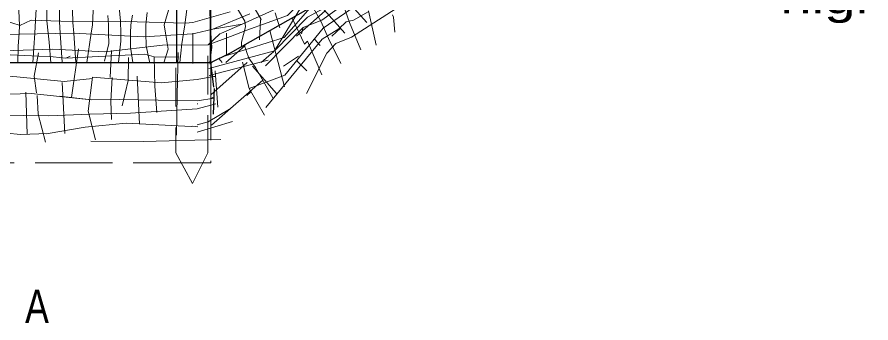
# Model space of a CAD drawing. Extents: x 1083.1 to 1117.1, y 672.5 to 716.5.
# Drawn here: x 1093.956 to 1098.058, y 709.948 to 711.418 of the extents above; entities that cross this region are included whole.
import ezdxf
from ezdxf.enums import TextEntityAlignment as Align

# ---------------------------------------------------------------- set-up
doc = ezdxf.new("R2010")
doc.units = 0
doc.header["$LTSCALE"] = 0.062
doc.linetypes.add('LONG_DASHED', pattern=[7.5, 6, -1.5])
doc.linetypes.add('MEDIUM_DASHED', pattern=[4.5, 3, -1.5])
doc.layers.add('1', color=7, linetype='Continuous', lineweight=13)

msp = doc.modelspace()

# ---------------------------------------------------------------- linework, layer by layer
at = {"layer": '1', "lineweight": 25}
for p, q in [((1094.98183, 711.247), (1098.69967, 713.3535)), ((1094.72208, 712.82583), (1094.72208, 711.20083)), ((1094.88383, 712.82583), (1094.88383, 711.19133)), ((1094.88667, 711.19942), (1094.98183, 711.247)), ((1091.47983, 711.19942), (1094.88667, 711.19942)), ((1094.90133, 711.08083), (1094.88667, 711.19942)), ((1094.89983, 710.95233), (1094.90467, 711.07442))]:
    msp.add_line(p, q, dxfattribs=at)
at = {"layer": '1'}
for p, q in [((1094.04458, 711.40167), (1094.0705, 711.79283)), ((1094.22492, 711.39167), (1094.21133, 711.768)), ((1095.44575, 711.60675), (1095.63625, 711.39142)), ((1094.95658, 711.556), (1095.05117, 711.39783)), ((1095.19258, 711.25575), (1095.36125, 711.53283)), ((1095.34167, 711.55475), (1095.5315, 711.34017)), ((1095.56717, 711.53617), (1095.35125, 711.41742)), ((1095.07175, 711.50775), (1095.12933, 711.4065)), ((1095.55317, 711.3915), (1095.51583, 711.49642)), ((1095.84, 711.50142), (1095.56283, 711.32108)), ((1094.32325, 711.48133), (1094.31858, 711.38033)), ((1094.69125, 711.47833), (1094.66233, 711.38033)), ((1094.77175, 711.45508), (1094.76283, 711.38033)), ((1095.36492, 711.46267), (1095.2395, 711.31933)), ((1095.29858, 711.32725), (1095.43575, 711.44858)), ((1095.41625, 711.398), (1095.37575, 711.46875)), ((1095.682, 711.28283), (1095.64483, 711.44775)), ((1094.39175, 711.42658), (1094.395, 711.38033)), ((1094.51142, 711.42683), (1094.50258, 711.38033)), ((1094.58058, 711.44), (1094.57542, 711.38033)), ((1094.80108, 711.3925), (1094.9805, 711.44392)), ((1095.07425, 711.4335), (1094.89725, 711.3595)), ((1095.35125, 711.41742), (1095.19275, 711.25608)), ((1095.19667, 711.43817), (1095.21867, 711.366)), ((1095.33717, 711.28725), (1095.27733, 711.41375)), ((1094.02492, 711.40308), (1093.96908, 711.378)), ((1094.02492, 711.40308), (1094.16708, 711.39875)), ((1094.76575, 711.38842), (1094.80108, 711.3925)), ((1095.03708, 711.38467), (1094.89725, 711.3595)), ((1094.93775, 711.34133), (1095.03708, 711.38467)), ((1095.05117, 711.39783), (1095.05308, 711.37083)), ((1095.3305, 711.36825), (1095.14967, 711.18367)), ((1095.42708, 711.36533), (1095.24258, 711.13975)), ((1095.3305, 711.36825), (1095.32258, 711.33817)), ((1095.4685, 711.32725), (1095.51025, 711.36442)), ((1095.53733, 711.39517), (1095.50283, 711.36133)), ((1095.60717, 711.26058), (1095.55317, 711.3915)), ((1094.80058, 711.34133), (1094.80058, 711.19592)), ((1094.87408, 711.28517), (1094.98183, 711.32558)), ((1094.93058, 711.33825), (1094.93775, 711.34133)), ((1094.96233, 711.34133), (1094.96233, 711.23933)), ((1094.98183, 711.32558), (1095.05958, 711.35475)), ((1095.171, 711.35417), (1095.24125, 711.08325)), ((1095.50283, 711.36133), (1095.422, 711.31258)), ((1094.11008, 711.29833), (1094.11825, 711.199)), ((1094.39767, 711.29067), (1094.37675, 711.20667)), ((1094.45475, 711.30275), (1094.44308, 711.20117)), ((1094.74808, 711.28958), (1094.73767, 711.20008)), ((1094.95875, 711.19942), (1095.05242, 711.28225)), ((1095.2395, 711.31933), (1094.99367, 711.24308)), ((1095.06933, 711.22117), (1095.04675, 711.28467)), ((1095.422, 711.31258), (1095.15117, 710.98317)), ((1095.41967, 711.141), (1095.352, 711.30317)), ((1095.38675, 711.31083), (1095.41242, 711.28183)), ((1095.48792, 711.29083), (1095.4445, 711.24508)), ((1095.56283, 711.32108), (1095.48792, 711.29083)), ((1093.96183, 711.27875), (1093.9595, 711.19692)), ((1094.0375, 711.27117), (1094.03283, 711.19908)), ((1094.03808, 711.13417), (1094.05992, 711.247)), ((1094.21767, 711.03108), (1094.25175, 711.2655)), ((1094.4035, 711.1285), (1094.40983, 711.25708)), ((1094.50125, 711.27325), (1094.51292, 711.20008)), ((1094.57583, 711.27975), (1094.59442, 711.19683)), ((1094.68292, 711.26342), (1094.66083, 711.19792)), ((1095.19275, 711.25608), (1094.87767, 711.17125)), ((1094.89158, 711.27267), (1094.88158, 711.20117)), ((1094.94567, 711.22808), (1094.99367, 711.24308)), ((1095.12892, 711.19942), (1095.18917, 711.25267)), ((1095.34733, 711.05025), (1095.4445, 711.24508)), ((1093.9235, 711.23625), (1094.13008, 711.22725)), ((1094.13008, 711.22725), (1094.19125, 711.22)), ((1094.49008, 711.1135), (1094.49242, 711.22475)), ((1094.6155, 711.22767), (1094.73508, 711.22492)), ((1094.87925, 711.13775), (1095.16317, 711.21175)), ((1094.92517, 711.21867), (1094.94217, 711.19942)), ((1095.07158, 711.07575), (1095.03967, 711.20108)), ((1095.23675, 711.18292), (1095.30767, 711.2305)), ((1095.34783, 711.16), (1095.29842, 711.20992)), ((1094.88667, 711.195), (1094.89167, 711.19942)), ((1094.88667, 711.04467), (1095.06183, 711.19942)), ((1094.90842, 711.16008), (1094.92125, 710.98492)), ((1095.08667, 711.18275), (1095.20292, 711.05133)), ((1095.10192, 711.17525), (1095.18483, 711.03025)), ((1094.05033, 711.05408), (1094.03808, 711.13417)), ((1094.1825, 711.10917), (1094.31908, 711.12283)), ((1094.40742, 711.01383), (1094.41317, 711.12775)), ((1094.54433, 710.90425), (1094.53317, 711.13383)), ((1094.64808, 711.10217), (1094.82192, 711.11892)), ((1094.82192, 711.11892), (1094.90033, 711.133)), ((1094.90033, 711.133), (1094.90983, 711.13242)), ((1095.24258, 711.13975), (1095.07158, 711.07575)), ((1094.1725, 711.104), (1094.18592, 710.85825)), ((1094.46142, 710.99233), (1094.49008, 711.1135)), ((1094.89108, 710.89858), (1095.13642, 711.11542)), ((1094.00475, 710.855), (1093.99875, 711.05783)), ((1094.05292, 711.04217), (1094.05808, 710.95092)), ((1094.31392, 711.0205), (1094.1595, 711.0375)), ((1095.05983, 711.04158), (1095.0795, 711.05908)), ((1095.07158, 711.07575), (1095.14517, 710.94675)), ((1094.4095, 710.92567), (1094.40742, 711.01383)), ((1094.821, 711.00175), (1094.82433, 711.00175)), ((1094.90258, 711.02933), (1094.82192, 711.01642)), ((1094.82192, 710.97675), (1094.91058, 711.00192)), ((1094.88492, 711.02633), (1094.90042, 711.03267)), ((1094.82192, 710.97675), (1094.50158, 710.95608)), ((1094.97617, 710.97575), (1094.87508, 710.915)), ((1093.75225, 710.94892), (1094.10958, 710.94425)), ((1094.05808, 710.95092), (1094.09375, 710.81642)), ((1094.82192, 710.86558), (1094.99183, 710.9165)), ((1094.82192, 710.9005), (1094.87508, 710.915)), ((1094.47992, 710.90892), (1094.51217, 710.90658)), ((1094.79292, 710.89233), (1094.51217, 710.90658)), ((1094.79292, 710.89233), (1094.79975, 710.89325)), ((1094.79975, 710.89325), (1094.82433, 710.89108)), ((1093.97242, 710.85442), (1093.90783, 710.86117)), ((1094.10533, 710.8595), (1093.97242, 710.85442)), ((1094.56283, 710.82083), (1094.3105, 710.82133)), ((1094.93533, 710.8295), (1094.56283, 710.82083))]:
    msp.add_line(p, q, dxfattribs=at)
at = {"layer": '1', "linetype": 'MEDIUM_DASHED'}
for p, q in [((1094.873, 711.23267), (1094.873, 710.76583)), ((1094.719, 711.17425), (1094.719, 710.76583)), ((1094.719, 710.76583), (1094.79917, 710.61883)), ((1094.79917, 710.61883), (1094.873, 710.76583))]:
    msp.add_line(p, q, dxfattribs=at)
at = {"layer": '1'}
for points in [[(1094.43817, 711.96875), (1094.44375, 711.73108), (1094.43633, 711.58558), (1094.45367, 711.398)], [(1094.16267, 711.83467), (1094.16017, 711.59392), (1094.16017, 711.39525)], [(1095.05958, 711.35475), (1095.25608, 711.42583), (1095.49575, 711.67175), (1095.78192, 711.81883)], [(1094.09925, 711.40067), (1094.09975, 711.67042), (1094.11067, 711.76058)], [(1093.96358, 711.6655), (1093.96125, 711.524), (1093.96867, 711.37775)], [(1095.42117, 711.40275), (1095.64808, 711.569), (1095.79392, 711.66242)], [(1095.42708, 711.36533), (1095.6785, 711.53975), (1095.8755, 711.65675)], [(1094.88083, 711.47408), (1094.88792, 711.34133), (1094.89158, 711.27267)], [(1095.03708, 711.38467), (1095.20125, 711.45767), (1095.22025, 711.46975)], [(1093.69192, 711.40308), (1093.77825, 711.41267), (1093.89117, 711.40342), (1093.97117, 711.378)], [(1095.12933, 711.4065), (1095.12608, 711.40317), (1095.12142, 711.30925)], [(1095.64283, 711.44417), (1095.57292, 711.40267), (1095.53733, 711.39517)], [(1095.77075, 711.34575), (1095.764, 711.4175), (1095.75908, 711.4285)], [(1093.96867, 711.37775), (1093.96608, 711.34133), (1093.96183, 711.27875)], [(1094.04458, 711.40167), (1094.04125, 711.34133), (1094.0375, 711.27117)], [(1094.09925, 711.40067), (1094.1055, 711.34133), (1094.11008, 711.29833)], [(1094.16017, 711.39525), (1094.16375, 711.34133), (1094.173, 711.20117)], [(1094.16708, 711.39875), (1094.475, 711.39617), (1094.76575, 711.38842)], [(1094.22492, 711.39167), (1094.22875, 711.34133), (1094.23933, 711.199)], [(1094.31858, 711.38033), (1094.31275, 711.34133), (1094.29175, 711.20008)], [(1094.395, 711.38033), (1094.39617, 711.34133), (1094.39767, 711.29067)], [(1094.45367, 711.398), (1094.45433, 711.34133), (1094.45475, 711.30275)], [(1094.50258, 711.38033), (1094.50208, 711.34133), (1094.50125, 711.27325)], [(1094.57542, 711.38033), (1094.57558, 711.34133), (1094.57583, 711.27975)], [(1094.66233, 711.38033), (1094.66917, 711.34133), (1094.68292, 711.26342)], [(1094.76283, 711.38033), (1094.7565, 711.34133), (1094.74808, 711.28958)], [(1095.05308, 711.37083), (1095.03417, 711.29725), (1095.03417, 711.27433)], [(1095.42117, 711.40275), (1095.3305, 711.36825), (1095.32858, 711.36983)], [(1095.51233, 711.195), (1095.4525, 711.31533), (1095.41625, 711.398)], [(1093.88058, 711.33525), (1094.22583, 711.34017), (1094.5655, 711.324), (1094.79867, 711.33775)], [(1093.89092, 711.25608), (1094.12583, 711.26417), (1094.37758, 711.25125), (1094.65517, 711.28358), (1094.87408, 711.28517), (1094.93058, 711.33825)], [(1094.89725, 711.3595), (1094.81492, 711.34133), (1094.79867, 711.33775)], [(1095.352, 711.30317), (1095.33717, 711.28725), (1095.33517, 711.29342)], [(1094.72283, 710.85042), (1094.726, 711.04375), (1094.72975, 711.24875)], [(1094.57075, 711.23967), (1094.19125, 711.22), (1094.21117, 711.23025)], [(1094.628, 710.95983), (1094.61817, 711.08667), (1094.6155, 711.22767), (1094.57075, 711.23967)], [(1095.10192, 711.17525), (1095.06933, 711.22117), (1095.06725, 711.22525)], [(1093.783, 711.14417), (1093.95533, 711.13108), (1094.1825, 711.10917)], [(1094.3335, 710.8285), (1094.29833, 710.96592), (1094.31933, 711.12867), (1094.64808, 711.10217)], [(1093.60383, 711.0375), (1094.02492, 711.05158), (1094.31392, 711.0205)], [(1094.31392, 711.0205), (1094.44675, 711.02275), (1094.82192, 711.01642)], [(1094.50158, 710.95608), (1094.30567, 710.95183), (1094.10958, 710.94425)], [(1094.47992, 710.90892), (1094.28367, 710.88892), (1094.10533, 710.8595), (1094.09883, 710.85708)]]:
    msp.add_lwpolyline(points, dxfattribs=at)
msp.add_lwpolyline([(1091.47983, 711.19942), (1091.47983, 711.69942), (1094.88667, 711.69942), (1094.88667, 711.19942)], close=True, dxfattribs=at)
at = {"layer": '1', "linetype": 'LONG_DASHED'}
msp.add_lwpolyline([(1091.47983, 711.19942), (1094.88667, 711.19942), (1094.88667, 710.71767), (1091.49483, 710.71767)], close=True, dxfattribs=at)

# ---------------------------------------------------------------- texts
at = {"layer": '1', "width": 1.3}
msp.add_text('higher than Point "B"', height=0.156, dxfattribs=at).set_placement((1098.87217, 711.43608), align=Align.CENTER)
at = {"layer": '1', "width": 0.8}
msp.add_text('A', height=0.16, dxfattribs=at).set_placement((1093.995, 709.9485))

doc.saveas('drawing.dxf')
